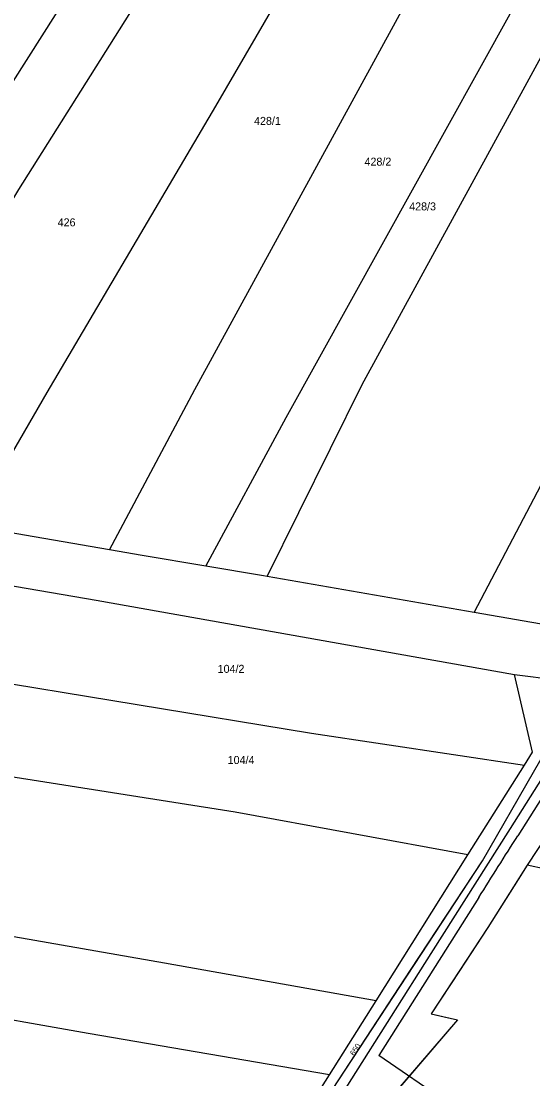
# Model space of a CAD drawing. Extents: x -746176 to -739709, y -1128407 to -1124482.
# Drawn here: x -743303 to -743194.3, y -1127186.5 to -1126961.9 of the extents above; entities that cross this region are included whole.
import ezdxf

# ---------------------------------------------------------------- set-up
doc = ezdxf.new("R2010")
doc.units = 0
for name, color, linetype in [('Vrstva 18', 7, 'Continuous'), ('Vrstva 29', 7, 'Continuous'), ('Vrstva 33', 7, 'Continuous'), ('Vrstva 34', 7, 'Continuous'), ('Vrstva 42', 7, 'Continuous'), ('Vrstva 5', 7, 'Continuous')]:
    doc.layers.add(name, color=color, linetype=linetype)

msp = doc.modelspace()

# ---------------------------------------------------------------- linework, layer by layer
at = {"layer": 'Vrstva 18'}
msp.add_lwpolyline([(-743072.49, -1126932.75), (-743098.65, -1126974.15), (-743125.94, -1127017.38), (-743152.6, -1127059.61), (-743175.02, -1127095.12), (-743199.16, -1127133.35), (-743215.97, -1127159.94), (-743232.82, -1127186.51), (-743247.46, -1127209.81), (-743254.52, -1127221.64), (-743261.3, -1127233.69), (-743264.16, -1127239.2), (-743264.86, -1127241.11), (-743267.34, -1127245.82), (-743268.29, -1127247.16), (-743271.71, -1127253.75), (-743281.12, -1127274.2), (-743291.92, -1127301.42), (-743296.72, -1127315.22), (-743301.12, -1127329.13), (-743306.79, -1127349.51)], dxfattribs=at)
at = {"layer": 'Vrstva 29'}
for points in [[(-743178.71, -1127105.09), (-743197.53, -1127134.89)], [(-743205.82, -1127148.01), (-743227.07, -1127181.59)]]:
    msp.add_lwpolyline(points, dxfattribs=at)
msp.add_arc((-755881.53, -1119127.65), 15000, 327.677064, 327.736346, dxfattribs=at)
at = {"layer": 'Vrstva 33'}
for p, q in [((-743284.26, -1127074.14), (-743313.92, -1127069.06)), ((-743206.78, -1127087.5), (-743250.75, -1127079.85)), ((-743180.08, -1127092.14), (-743206.78, -1127087.5)), ((-743198.26, -1127100.66), (-743183.34, -1127102.57)), ((-743208.12, -1127138.99), (-743196.1, -1127119.89)), ((-743183.01, -1127122.02), (-743195.51, -1127141.13)), ((-743227.63, -1127169.97), (-743208.12, -1127138.99)), ((-743237.55, -1127185.73), (-743227.63, -1127169.97))]:
    msp.add_line(p, q, dxfattribs=at)
for points in [[(-743343.4, -1127064.01), (-743303.47, -1126997.62), (-743275.93, -1126953.86), (-743239.29, -1126892.07)], [(-743359.71, -1127061.21), (-743292.37, -1126955.23), (-743255.64, -1126895.06)], [(-743313.92, -1127069.06), (-743297.49, -1127040.77), (-743261.68, -1126979.9), (-743236.45, -1126936.5), (-743215.19, -1126899.42)], [(-743284.26, -1127074.14), (-743266.09, -1127040.1), (-743193, -1126906.14)], [(-743263.8, -1127077.63), (-743246.71, -1127046.03), (-743171.59, -1126910.6)], [(-743250.75, -1127079.85), (-743230.59, -1127039.01), (-743190.96, -1126966.49), (-743161.41, -1126915.91)], [(-743206.78, -1127087.5), (-743159.7, -1126997.73), (-743124.42, -1126927.65)], [(-743263.8, -1127077.63), (-743277.29, -1127075.34), (-743284.26, -1127074.14)], [(-743250.75, -1127079.85), (-743251.53, -1127079.71), (-743263.8, -1127077.63)], [(-743311.47, -1127080.65), (-743287.04, -1127084.88), (-743198.26, -1127100.66)], [(-743196.1, -1127119.89), (-743194.38, -1127117.16), (-743198.26, -1127100.66)], [(-743315.45, -1127100.94), (-743241.34, -1127113.11), (-743196.1, -1127119.89)], [(-743280.26, -1127263.68), (-743264.54, -1127233.06), (-743246.95, -1127204.21), (-743235.54, -1127186.77), (-743205.03, -1127140.21), (-743183.34, -1127102.57)], [(-743227.63, -1127169.97), (-743272.53, -1127161.95), (-743339.46, -1127150.28), (-743422.36, -1127136.74), (-743485.93, -1127125.07), (-743521.87, -1127115.17), (-743538.97, -1127107.07)], [(-743208.12, -1127138.99), (-743257.58, -1127129.9), (-743320.04, -1127120.06)], [(-743237.55, -1127185.73), (-743288.76, -1127176.89), (-743377.84, -1127161.22), (-743451.69, -1127150.21), (-743484.81, -1127143.57), (-743511.45, -1127136.91), (-743530.98, -1127131.21), (-743549.04, -1127122.29)], [(-743195.51, -1127141.13), (-743196.63, -1127142.85), (-743203.92, -1127154.43), (-743215.95, -1127172.74), (-743210.36, -1127174.02), (-743237.28, -1127205.49), (-743245.75, -1127220.06), (-743259.48, -1127245.93)], [(-743121.01, -1127162.08), (-743132.72, -1127158.77), (-743148.75, -1127152.44), (-743172.16, -1127146.26), (-743195.51, -1127141.13)], [(-743247.25, -1127201.23), (-743244.15, -1127196.22), (-743237.55, -1127185.73)]]:
    msp.add_lwpolyline(points, dxfattribs=at)
at = {"layer": 'Vrstva 34'}
msp.add_line((-743187.51, -1127208.64), (-743227.07, -1127181.59), dxfattribs=at)
at = {"layer": 'Vrstva 5'}
msp.add_lwpolyline([(-743235.54, -1127186.77), (-743220.29, -1127163.49), (-743205.03, -1127140.21), (-743194.19, -1127121.39), (-743183.34, -1127102.57), (-743177.48, -1127103.58), (-743171.62, -1127104.6), (-743177.32, -1127113.31), (-743183.01, -1127122.02), (-743189.26, -1127131.57), (-743195.51, -1127141.13), (-743203.92, -1127154.43), (-743209.94, -1127163.59), (-743215.95, -1127172.74), (-743213.16, -1127173.38), (-743210.36, -1127174.02), (-743223.82, -1127189.76)], dxfattribs=at)

# ---------------------------------------------------------------- texts
at = {"layer": 'Vrstva 42'}
for s, p in [('428/1', (-743253.54, -1126983.9)), ('428/2', (-743230.08, -1126992.56)), ('428/3', (-743220.59, -1127002.06)), ('426', (-743295.25, -1127005.45)), ('104/2', (-743261.27, -1127100.3)), ('104/4', (-743259.14, -1127119.66))]:
    msp.add_text(s, height=1.7, dxfattribs=at).set_placement(p)
msp.add_text('650', height=1.19, rotation=56, dxfattribs=at).set_placement((-743232.29, -1127181.76))

doc.saveas('drawing.dxf')
